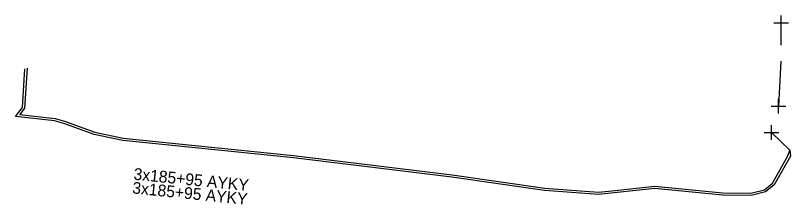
# Model space of a CAD drawing. Extents: x -536148 to -535465, y -1201639 to -1201298.
# Drawn here: x -536148.2 to -536082.1, y -1201323.2 to -1201307.1 of the extents above; entities that cross this region are included whole.
import ezdxf

# ---------------------------------------------------------------- set-up
doc = ezdxf.new("R2010")
doc.units = 0
for name, color, linetype in [('CHRAN_NN', 7, 'Continuous'), ('ELE_EON', 7, 'Continuous'), ('KN_VKP_HRAN_NEZNATELNÁ', 7, 'Continuous'), ('PROJEKT', 7, 'Continuous'), ('ZRUŠENO', 7, 'Continuous')]:
    doc.layers.add(name, color=color, linetype=linetype)

# ---------------------------------------------------------------- blocks, each defined once
blk = doc.blocks.new('NN800')
at = {"layer": 'ELE_EON'}
for points in [[(-0.442, 0.442), (0.442, -0.442)], [(-0.442, -0.442), (0.442, 0.442)]]:
    blk.add_lwpolyline(points, dxfattribs=at)

msp = doc.modelspace()

# ---------------------------------------------------------------- linework, layer by layer
at = {"layer": 'CHRAN_NN'}
for points in [[(-536082.888, -1201309.606), (-536082.888, -1201307.714)], [(-536082.917, -1201310.983), (-536083.102, -1201314.806)], [(-536082.138, -1201318.553), (-536083.706, -1201317.048)]]:
    msp.add_lwpolyline(points, dxfattribs=at)
at = {"layer": 'PROJEKT'}
msp.add_lwpolyline([(-536147.155, -1201311.56), (-536147.372, -1201314.977), (-536147.777, -1201315.506), (-536144.78, -1201315.839), (-536143.972, -1201316.08), (-536141.395, -1201317.011), (-536138.977, -1201317.526), (-536132.83, -1201318.153), (-536124.444, -1201318.993), (-536110.921, -1201320.645), (-536103.025, -1201321.773), (-536098.446, -1201322.118), (-536097.03, -1201321.983), (-536093.653, -1201321.617), (-536087.88, -1201322.18), (-536085.459, -1201322.19), (-536084.311, -1201321.918), (-536083.625, -1201321.365), (-536082.306, -1201319.038), (-536082.138, -1201318.553), (-536082.089, -1201319.061), (-536083.47, -1201321.496), (-536084.22, -1201322.102), (-536085.436, -1201322.39), (-536087.89, -1201322.38), (-536093.652, -1201321.818), (-536098.444, -1201322.318), (-536103.046, -1201321.972), (-536110.948, -1201320.844), (-536124.466, -1201319.192), (-536132.85, -1201318.352), (-536139.008, -1201317.724), (-536141.45, -1201317.204), (-536144.034, -1201316.27), (-536144.82, -1201316.036), (-536148.152, -1201315.666), (-536147.568, -1201314.903), (-536147.36, -1201311.612)], dxfattribs=at)

# ---------------------------------------------------------------- block references
at = {"layer": 'KN_VKP_HRAN_NEZNATELNÁ'}
for p, rotation in [((-536082.888, -1201307.714), 44.999999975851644), ((-536083.102, -1201314.806), 45), ((-536083.706, -1201317.048), 45.00000009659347)]:
    msp.add_blockref('NN800', p, dxfattribs=dict(at, rotation=rotation))

# ---------------------------------------------------------------- texts
at = {"layer": 'ZRUŠENO'}
for rotation, p in [(354.28, (-536138.124, -1201321.047)), (354.279, (-536138.231, -1201322.221))]:
    msp.add_text('3x185+95 AYKY', height=1, rotation=rotation, dxfattribs=at).set_placement(p)

doc.saveas('drawing.dxf')
